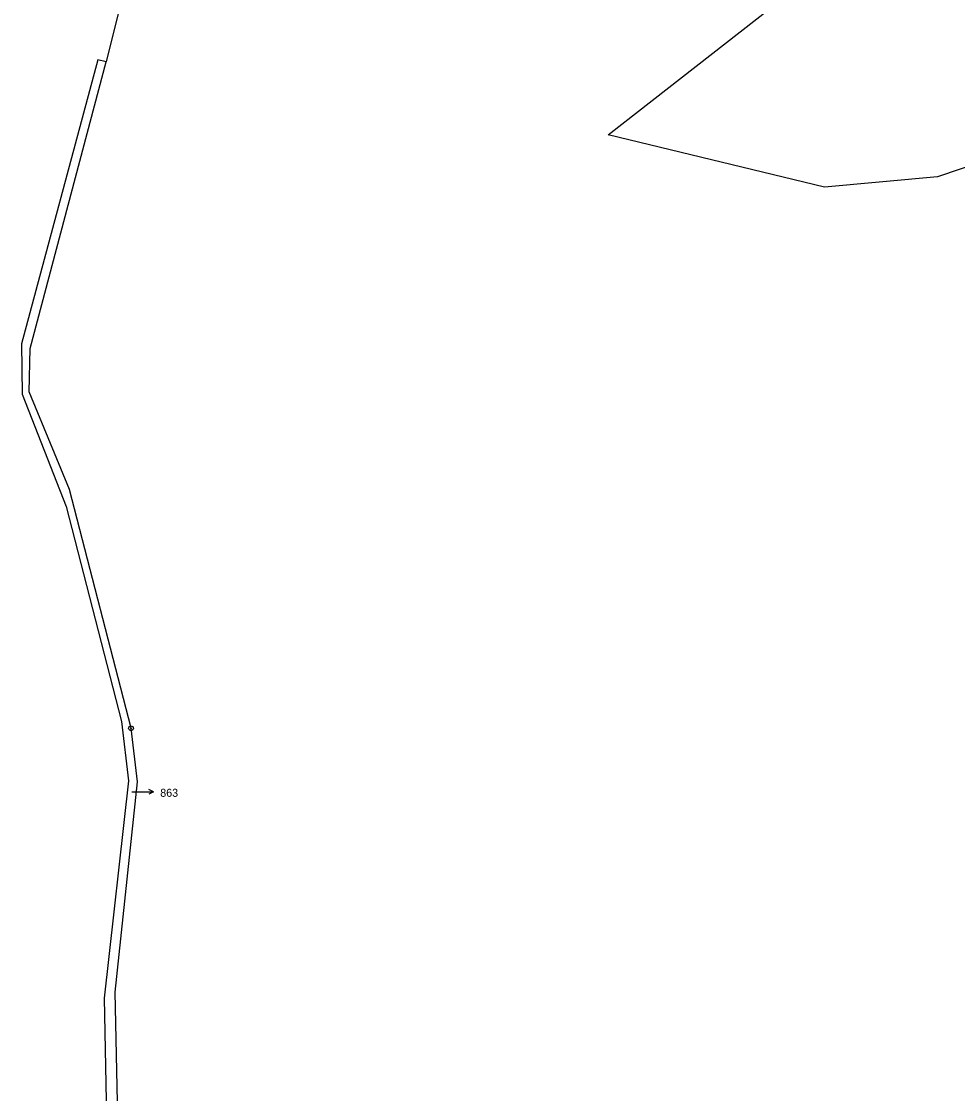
# Model space of a CAD drawing. Extents: x -791032 to -787751, y -1106872 to -1104403.
# Drawn here: x -790741.7 to -790542.9, y -1106274.5 to -1106046.8 of the extents above; entities that cross this region are included whole.
import ezdxf

# ---------------------------------------------------------------- set-up
doc = ezdxf.new("R2010")
doc.units = 0
for name, color, linetype in [('Komunikace', 7, 'Continuous'), ('Vrstva 1', 7, 'Continuous'), ('Vrstva 14', 7, 'Continuous'), ('Vrstva 16', 7, 'Continuous'), ('Vrstva 28', 7, 'Continuous'), ('Vrstva 4', 7, 'Continuous')]:
    doc.layers.add(name, color=color, linetype=linetype)

msp = doc.modelspace()

# ---------------------------------------------------------------- linework, layer by layer
at = {"layer": 'Komunikace'}
msp.add_line((-790718.2, -1106210.44), (-790716.61, -1106210.45), dxfattribs=at)
at = {"layer": 'Vrstva 1'}
for p, q in [((-790617.06, -1106070.88), (-790569.98, -1106034.1)), ((-790739.8, -1106116.27), (-790723.67, -1106055.39)), ((-790571.11, -1106082.02), (-790617.06, -1106070.88)), ((-790522.93, -1106071.55), (-790547.1, -1106079.85)), ((-790547.1, -1106079.85), (-790571.11, -1106082.02)), ((-790740.02, -1106125.5), (-790739.8, -1106116.27)), ((-790731.44, -1106146.22), (-790740.02, -1106125.5)), ((-790718.41, -1106196.95), (-790731.44, -1106146.22)), ((-790717.05, -1106208.34), (-790718.41, -1106196.95)), ((-790721.76, -1106253.01), (-790717.05, -1106208.34)), ((-790721.2, -1106281.5), (-790721.76, -1106253.01))]:
    msp.add_line(p, q, dxfattribs=at)
at = {"layer": 'Vrstva 16'}
for p, q in [((-790716.61, -1106210.45), (-790713.61, -1106210.469)), ((-790713.61, -1106210.469), (-790714.613, -1106210.963)), ((-790713.61, -1106210.469), (-790714.606, -1106209.963))]:
    msp.add_line(p, q, dxfattribs=at)
at = {"layer": 'Vrstva 28'}
for radius in [0.5, 0.01]:
    msp.add_circle((-790718.41, -1106196.95), radius, dxfattribs=at)
at = {"layer": 'Vrstva 4'}
for p, q in [((-790716.99, -1106028.3), (-790723.67, -1106055.39)), ((-790725.47, -1106054.99), (-790741.68, -1106115.31)), ((-790723.67, -1106055.39), (-790725.47, -1106054.99)), ((-790741.68, -1106115.31), (-790741.56, -1106126.01)), ((-790741.56, -1106126.01), (-790732.2, -1106149.85)), ((-790732.2, -1106149.85), (-790720.46, -1106195.48)), ((-790720.46, -1106195.48), (-790718.94, -1106208.08)), ((-790718.94, -1106208.08), (-790724.12, -1106254.29)), ((-790724.12, -1106254.29), (-790723.53, -1106281.99))]:
    msp.add_line(p, q, dxfattribs=at)

# ---------------------------------------------------------------- texts
at = {"layer": 'Vrstva 14'}
msp.add_text('863', height=0.1, dxfattribs=at).set_placement((-790718.33, -1106210.44))
at = {"layer": 'Vrstva 16'}
msp.add_text('863', height=1.7, dxfattribs=at).set_placement((-790712.2, -1106211.5))

doc.saveas('drawing.dxf')
